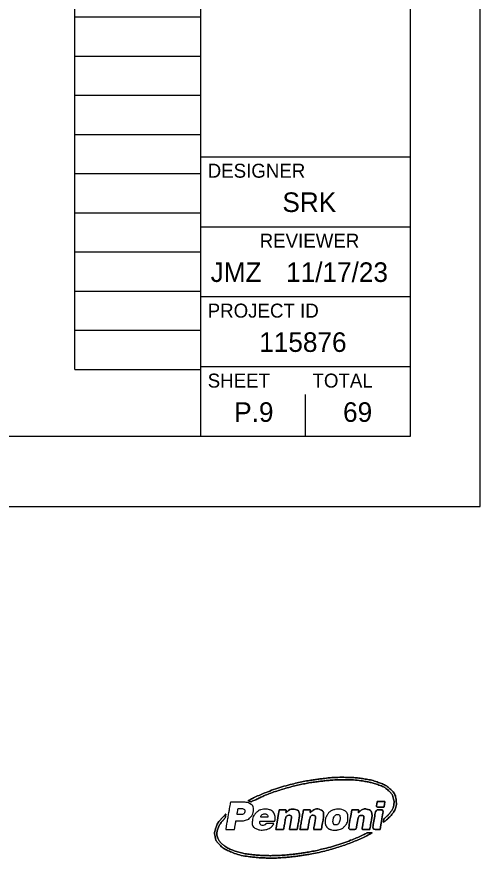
# Model space of a CAD drawing. Extents: x 0 to 63.3, y -2.5 to 22.
# Drawn here: x 30.68 to 34, y -2.51 to 3.5 of the extents above; entities that cross this region are included whole.
import ezdxf

# ---------------------------------------------------------------- set-up
doc = ezdxf.new("R2010")
doc.units = 0
for name, color, linetype in [('SH_Border', 7, 'Continuous'), ('SH_Cut_Line', 7, 'Continuous'), ('SH_Data', 7, 'Continuous')]:
    doc.layers.add(name, color=color, linetype=linetype)

msp = doc.modelspace()

# ---------------------------------------------------------------- linework, layer by layer
at = {"layer": 'SH_Border'}
for p, q in [((32, 0.5), (32, 21.5)), ((32, 2.5), (33.5, 2.5)), ((32, 2), (33.5, 2)), ((32, 1.5), (33.5, 1.5)), ((32, 1), (33.5, 1)), ((32.4801, -2.2212), (32.4295, -2.2212))]:
    msp.add_line(p, q, dxfattribs=at)
msp.add_lwpolyline([(1.5, 21.5), (33.5, 21.5), (33.5, 0.5), (1.5, 0.5)], close=True, dxfattribs=at)
for points, degree in [([(32.339, -2.1034), (32.3459, -2.1056), (32.3519, -2.1078), (32.358, -2.1095), (32.3601, -2.11), (32.3628, -2.1098), (32.3647, -2.1089), (32.3935, -2.0957), (32.4219, -2.0816), (32.4509, -2.0691), (32.4921, -2.0514), (32.5345, -2.0366), (32.5774, -2.0234), (32.6194, -2.0105), (32.6618, -1.9993), (32.7047, -1.9898), (32.7445, -1.981), (32.7845, -1.9732), (32.825, -1.968), (32.8569, -1.9639), (32.8889, -1.96), (32.921, -1.9571), (32.9462, -1.9549), (32.9715, -1.9539), (32.9968, -1.9532), (33.0519, -1.9517), (33.1068, -1.9542), (33.1614, -1.9623), (33.191, -1.9667), (33.2203, -1.9727), (33.2489, -1.9818), (33.2843, -1.9931), (33.3181, -2.0076), (33.346, -2.033), (33.3612, -2.0467), (33.3728, -2.0629), (33.3781, -2.0829), (33.3826, -2.1), (33.3843, -2.1174), (33.3813, -2.135), (33.3779, -2.1552), (33.368, -2.1723), (33.3554, -2.1881), (33.3434, -2.2033), (33.3294, -2.2165), (33.3147, -2.2291), (33.3132, -2.2304), (33.3116, -2.2321), (33.3111, -2.234), (33.3098, -2.2395), (33.3089, -2.2452), (33.3079, -2.2509), (33.3075, -2.2532), (33.3073, -2.2556), (33.3068, -2.2589), (33.3307, -2.2389), (33.3534, -2.2193), (33.372, -2.1955), (33.381, -2.184), (33.3886, -2.1716), (33.3937, -2.1578), (33.4006, -2.1393), (33.4009, -2.1203), (33.3987, -2.1009), (33.3948, -2.0665), (33.379, -2.0389), (33.3529, -2.0167), (33.329, -1.9965), (33.3014, -1.9828), (33.2722, -1.9721), (33.235, -1.9585), (33.1965, -1.9504), (33.1574, -1.9448), (33.1225, -1.9398), (33.0874, -1.9372), (33.0522, -1.9363), (32.9958, -1.9348), (32.9394, -1.9373), (32.8834, -1.9435), (32.8524, -1.947), (32.8216, -1.9515), (32.7908, -1.9561), (32.7456, -1.963), (32.7008, -1.9727), (32.6564, -1.9838), (32.5959, -1.9989), (32.5365, -2.0173), (32.4783, -2.0398), (32.4374, -2.0555), (32.3974, -2.0732), (32.3584, -2.0931), (32.3521, -2.0963), (32.346, -2.0997), (32.339, -2.1034)], 3), ([(32.339, -2.1034), (32.346, -2.0997), (32.3521, -2.0963), (32.3584, -2.0931), (32.3974, -2.0732), (32.4374, -2.0555), (32.4783, -2.0398), (32.5365, -2.0173), (32.5959, -1.9989), (32.6564, -1.9838), (32.7008, -1.9727), (32.7456, -1.963), (32.7908, -1.9561), (32.8216, -1.9515), (32.8524, -1.947), (32.8834, -1.9435), (32.9394, -1.9373), (32.9958, -1.9348), (33.0522, -1.9363), (33.0874, -1.9372), (33.1225, -1.9398), (33.1574, -1.9448), (33.1965, -1.9504), (33.235, -1.9585), (33.2722, -1.9721), (33.3014, -1.9828), (33.329, -1.9965), (33.3529, -2.0167), (33.379, -2.0389), (33.3948, -2.0665), (33.3987, -2.1009), (33.4009, -2.1203), (33.4006, -2.1393), (33.3937, -2.1578), (33.3886, -2.1716), (33.381, -2.184), (33.372, -2.1955), (33.3534, -2.2193), (33.3307, -2.2389), (33.3068, -2.2589), (33.3073, -2.2556), (33.3075, -2.2532), (33.3079, -2.2509), (33.3089, -2.2452), (33.3098, -2.2395), (33.3111, -2.234), (33.3116, -2.2321), (33.3132, -2.2304), (33.3147, -2.2291), (33.3294, -2.2165), (33.3434, -2.2033), (33.3554, -2.1881), (33.368, -2.1723), (33.3779, -2.1552), (33.3813, -2.135), (33.3843, -2.1174), (33.3826, -2.1), (33.3781, -2.0829), (33.3728, -2.0629), (33.3612, -2.0467), (33.346, -2.033), (33.3181, -2.0076), (33.2843, -1.9931), (33.2489, -1.9818), (33.2203, -1.9727), (33.191, -1.9667), (33.1614, -1.9623), (33.1068, -1.9542), (33.0519, -1.9517), (32.9968, -1.9532), (32.9715, -1.9539), (32.9462, -1.9549), (32.921, -1.9571), (32.8889, -1.96), (32.8569, -1.9639), (32.825, -1.968), (32.7845, -1.9732), (32.7445, -1.981), (32.7047, -1.9898), (32.6618, -1.9993), (32.6194, -2.0105), (32.5774, -2.0234), (32.5345, -2.0366), (32.4921, -2.0514), (32.4509, -2.0691), (32.4219, -2.0816), (32.3935, -2.0957), (32.3647, -2.1089), (32.3628, -2.1098), (32.3601, -2.11), (32.358, -2.1095), (32.3519, -2.1078), (32.3459, -2.1056), (32.339, -2.1034)], 3), ([(32.3504, -2.1223), (32.3379, -2.1163), (32.3244, -2.1142), (32.3107, -2.114), (32.2789, -2.1136), (32.2472, -2.1138), (32.2155, -2.1138), (32.2134, -2.1138), (32.2123, -2.1143), (32.212, -2.1165), (32.2083, -2.138), (32.2045, -2.1594), (32.2007, -2.1808), (32.1947, -2.2157), (32.1886, -2.2506), (32.1825, -2.2854), (32.1813, -2.2926), (32.18, -2.2998), (32.1788, -2.3071)], 3), ([(32.2521, -2.2472), (32.2596, -2.2472), (32.2665, -2.2472), (32.2735, -2.2472), (32.2865, -2.2472), (32.2994, -2.2474), (32.3122, -2.2447), (32.3288, -2.2411), (32.3438, -2.2346), (32.3556, -2.222), (32.3705, -2.2062), (32.3768, -2.1869), (32.3771, -2.1657), (32.3775, -2.1459), (32.3686, -2.1311), (32.3504, -2.1223)], 3), ([(32.2599, -2.2022), (32.2624, -2.188), (32.2648, -2.1745), (32.2673, -2.161), (32.2674, -2.1601), (32.2686, -2.1588), (32.2694, -2.1588), (32.2808, -2.1588), (32.2924, -2.1577), (32.3036, -2.1611), (32.314, -2.1642), (32.3177, -2.1706), (32.3157, -2.1812)], 3), ([(32.5317, -2.2161), (32.5277, -2.1917), (32.5147, -2.1747), (32.4908, -2.1668), (32.4777, -2.1625), (32.4642, -2.1619), (32.4507, -2.1636), (32.4286, -2.1665), (32.4095, -2.1756), (32.3941, -2.1919), (32.38, -2.2068), (32.3722, -2.2246), (32.3699, -2.2449), (32.3667, -2.2738), (32.379, -2.2978), (32.4083, -2.3074), (32.4242, -2.3126), (32.4404, -2.3128), (32.4567, -2.3104), (32.4743, -2.308), (32.4907, -2.3021), (32.5045, -2.2904), (32.5124, -2.2837), (32.5186, -2.2756), (32.523, -2.2656)], 3), ([(32.5375, -2.3087), (32.5383, -2.3089), (32.5388, -2.3091), (32.5393, -2.3091), (32.5563, -2.3091), (32.5733, -2.3091), (32.5903, -2.3092), (32.5928, -2.3092), (32.5933, -2.3078), (32.5936, -2.306), (32.595, -2.2978), (32.5963, -2.2897), (32.5978, -2.2815), (32.6009, -2.2639), (32.6038, -2.2463), (32.6075, -2.2288), (32.6095, -2.2196), (32.6141, -2.2116), (32.6242, -2.2089), (32.6372, -2.2054), (32.6506, -2.2082), (32.6485, -2.2277), (32.6469, -2.2419), (32.6441, -2.2559), (32.6417, -2.27), (32.6395, -2.2829), (32.6372, -2.2957), (32.6349, -2.3087), (32.6356, -2.3089), (32.6361, -2.3091), (32.6367, -2.3091), (32.6537, -2.3091), (32.6707, -2.3091), (32.6877, -2.3091), (32.6903, -2.3092), (32.6906, -2.3078), (32.691, -2.3057), (32.6951, -2.2817), (32.6994, -2.2578), (32.7035, -2.2339), (32.7056, -2.2218), (32.708, -2.2097), (32.7063, -2.1973), (32.7042, -2.1811), (32.6948, -2.1698), (32.679, -2.1658), (32.6573, -2.1605), (32.6376, -2.1645), (32.6205, -2.1792), (32.6167, -2.1824), (32.6132, -2.1858), (32.609, -2.1897), (32.6104, -2.1819), (32.6116, -2.1749), (32.6128, -2.1677), (32.5965, -2.1677), (32.5803, -2.1676), (32.5641, -2.1678), (32.5633, -2.1678), (32.562, -2.1692), (32.5618, -2.1701), (32.5608, -2.1744), (32.5601, -2.1788), (32.5593, -2.1831), (32.554, -2.2136), (32.5487, -2.2442), (32.5434, -2.2747), (32.5414, -2.286), (32.5395, -2.2973), (32.5375, -2.3087)], 3), ([(32.5375, -2.3087), (32.5395, -2.2973), (32.5414, -2.286), (32.5434, -2.2747), (32.5487, -2.2442), (32.554, -2.2136), (32.5593, -2.1831), (32.5601, -2.1788), (32.5608, -2.1744), (32.5618, -2.1701), (32.562, -2.1692), (32.5633, -2.1678), (32.5641, -2.1678), (32.5803, -2.1676), (32.5965, -2.1677), (32.6128, -2.1677), (32.6116, -2.1749), (32.6104, -2.1819), (32.609, -2.1897), (32.6132, -2.1858), (32.6167, -2.1824), (32.6205, -2.1792), (32.6376, -2.1645), (32.6573, -2.1605), (32.679, -2.1658), (32.6948, -2.1698), (32.7042, -2.1811), (32.7063, -2.1973), (32.708, -2.2097), (32.7056, -2.2218), (32.7035, -2.2339), (32.6994, -2.2578), (32.6951, -2.2817), (32.691, -2.3057), (32.6906, -2.3078), (32.6903, -2.3092), (32.6877, -2.3091), (32.6707, -2.3091), (32.6537, -2.3091), (32.6367, -2.3091), (32.6361, -2.3091), (32.6356, -2.3089), (32.6349, -2.3087), (32.6372, -2.2957), (32.6395, -2.2829), (32.6417, -2.27), (32.6441, -2.2559), (32.6469, -2.2419), (32.6485, -2.2277), (32.6506, -2.2082), (32.6372, -2.2054), (32.6242, -2.2089), (32.6141, -2.2116), (32.6095, -2.2196), (32.6075, -2.2288), (32.6038, -2.2463), (32.6009, -2.2639), (32.5978, -2.2815), (32.5963, -2.2897), (32.595, -2.2978), (32.5936, -2.306), (32.5933, -2.3078), (32.5928, -2.3092), (32.5903, -2.3092), (32.5733, -2.3091), (32.5563, -2.3091), (32.5393, -2.3091), (32.5388, -2.3091), (32.5383, -2.3089), (32.5375, -2.3087)], 3), ([(32.7105, -2.3086), (32.711, -2.3088), (32.7112, -2.309), (32.7114, -2.309), (32.7289, -2.309), (32.7463, -2.3091), (32.7637, -2.309), (32.7646, -2.309), (32.7662, -2.3075), (32.7664, -2.3065), (32.7695, -2.2894), (32.7723, -2.2722), (32.7755, -2.2552), (32.7773, -2.2449), (32.779, -2.2346), (32.782, -2.2247), (32.786, -2.211), (32.798, -2.2057), (32.811, -2.2084), (32.817, -2.2096), (32.8202, -2.2135), (32.8212, -2.2193), (32.8218, -2.2223), (32.822, -2.2255), (32.8215, -2.2284), (32.8199, -2.2397), (32.818, -2.2509), (32.8161, -2.2621), (32.8134, -2.2776), (32.8107, -2.2931), (32.808, -2.3085), (32.8084, -2.3087), (32.8085, -2.3089), (32.8086, -2.3089), (32.8261, -2.3089), (32.8437, -2.3091), (32.8612, -2.309), (32.8621, -2.309), (32.8636, -2.3071), (32.8638, -2.306), (32.8679, -2.2836), (32.872, -2.2613), (32.8756, -2.2389), (32.8776, -2.2269), (32.8796, -2.2148), (32.8796, -2.2027), (32.8797, -2.1872), (32.8736, -2.1738), (32.858, -2.1679), (32.8375, -2.1603), (32.8177, -2.1621), (32.7995, -2.1747), (32.7936, -2.1788), (32.7883, -2.1839), (32.7823, -2.189), (32.7835, -2.1817), (32.7846, -2.1748), (32.7858, -2.1677), (32.7694, -2.1677), (32.7535, -2.1677), (32.7376, -2.1676), (32.7347, -2.1676), (32.7349, -2.1694), (32.7345, -2.1713), (32.7304, -2.1951), (32.7262, -2.2189), (32.7221, -2.2428), (32.7182, -2.2647), (32.7144, -2.2867), (32.7105, -2.3086)], 3), ([(32.7105, -2.3086), (32.7144, -2.2867), (32.7182, -2.2647), (32.7221, -2.2428), (32.7262, -2.2189), (32.7304, -2.1951), (32.7345, -2.1713), (32.7349, -2.1694), (32.7347, -2.1676), (32.7376, -2.1676), (32.7535, -2.1677), (32.7694, -2.1677), (32.7858, -2.1677), (32.7846, -2.1748), (32.7835, -2.1817), (32.7823, -2.189), (32.7883, -2.1839), (32.7936, -2.1788), (32.7995, -2.1747), (32.8177, -2.1621), (32.8375, -2.1603), (32.858, -2.1679), (32.8736, -2.1738), (32.8797, -2.1872), (32.8796, -2.2027), (32.8796, -2.2148), (32.8776, -2.2269), (32.8756, -2.2389), (32.872, -2.2613), (32.8679, -2.2836), (32.8638, -2.306), (32.8636, -2.3071), (32.8621, -2.309), (32.8612, -2.309), (32.8437, -2.3091), (32.8261, -2.3089), (32.8086, -2.3089), (32.8085, -2.3089), (32.8084, -2.3087), (32.808, -2.3085), (32.8107, -2.2931), (32.8134, -2.2776), (32.8161, -2.2621), (32.818, -2.2509), (32.8199, -2.2397), (32.8215, -2.2284), (32.822, -2.2255), (32.8218, -2.2223), (32.8212, -2.2193), (32.8202, -2.2135), (32.817, -2.2096), (32.811, -2.2084), (32.798, -2.2057), (32.786, -2.211), (32.782, -2.2247), (32.779, -2.2346), (32.7773, -2.2449), (32.7755, -2.2552), (32.7723, -2.2722), (32.7695, -2.2894), (32.7664, -2.3065), (32.7662, -2.3075), (32.7646, -2.309), (32.7637, -2.309), (32.7463, -2.3091), (32.7289, -2.309), (32.7114, -2.309), (32.7112, -2.309), (32.711, -2.3088), (32.7105, -2.3086)], 3), ([(33.0535, -2.2166), (33.0522, -2.1945), (33.041, -2.1788), (33.0206, -2.1702), (33.0015, -2.1621), (32.9815, -2.1619), (32.9615, -2.1661), (32.9376, -2.1712), (32.9183, -2.1836), (32.9053, -2.2046), (32.904, -2.2067), (32.9028, -2.2088), (32.9016, -2.211), (32.9005, -2.2131), (32.8995, -2.2153), (32.8985, -2.2175), (32.8937, -2.2284), (32.8911, -2.2399), (32.8907, -2.252), (32.8906, -2.2544), (32.8906, -2.2568), (32.8907, -2.2592), (32.8911, -2.2671), (32.8927, -2.2743), (32.8955, -2.2805), (32.896, -2.2817), (32.8965, -2.2828), (32.8971, -2.2839), (32.8977, -2.285), (32.8983, -2.286), (32.899, -2.2871), (32.9014, -2.2907), (32.9042, -2.294), (32.9075, -2.2969), (32.9094, -2.2986), (32.9115, -2.3001), (32.9137, -2.3016), (32.9142, -2.3019), (32.9148, -2.3023), (32.9154, -2.3026), (32.9165, -2.3033), (32.9177, -2.304), (32.9189, -2.3046), (32.9208, -2.3056), (32.9227, -2.3065), (32.9247, -2.3073), (32.9358, -2.3118), (32.9474, -2.3134), (32.9593, -2.3137)], 3), ([(33.0812, -2.1678), (33.073, -2.2149), (33.0648, -2.2618), (33.0566, -2.3089), (33.0756, -2.3089), (33.0937, -2.3089), (33.1121, -2.3089), (33.1146, -2.2946), (33.117, -2.2805), (33.1195, -2.2665), (33.1219, -2.2536), (33.124, -2.2407), (33.1269, -2.2279), (33.13, -2.214), (33.1398, -2.207), (33.1532, -2.2077), (33.1618, -2.2082), (33.1669, -2.2128), (33.1677, -2.2213), (33.168, -2.2244), (33.168, -2.2275), (33.1675, -2.2306), (33.1643, -2.2495), (33.161, -2.2685), (33.1577, -2.2874), (33.1565, -2.2945), (33.1553, -2.3015), (33.1541, -2.3088), (33.1728, -2.3088), (33.1911, -2.3088), (33.2093, -2.3088), (33.2097, -2.3073), (33.2101, -2.3062), (33.2103, -2.305), (33.214, -2.2838), (33.2177, -2.2626), (33.2213, -2.2414), (33.2236, -2.2276), (33.2267, -2.2139), (33.2257, -2.1997), (33.2245, -2.1833), (33.2157, -2.1709), (33.2, -2.1664), (33.1751, -2.1593), (33.1533, -2.1654), (33.1348, -2.1834), (33.1328, -2.1853), (33.1309, -2.1872), (33.129, -2.1891), (33.1288, -2.189), (33.1285, -2.1888), (33.1283, -2.1887), (33.1295, -2.1818), (33.1306, -2.1749), (33.1318, -2.1678), (33.1147, -2.1678), (33.0982, -2.1678), (33.0812, -2.1678)], 3), ([(33.0812, -2.1678), (33.0982, -2.1678), (33.1147, -2.1678), (33.1318, -2.1678), (33.1306, -2.1749), (33.1295, -2.1818), (33.1283, -2.1887), (33.1285, -2.1888), (33.1288, -2.189), (33.129, -2.1891), (33.1309, -2.1872), (33.1328, -2.1853), (33.1348, -2.1834), (33.1533, -2.1654), (33.1751, -2.1593), (33.2, -2.1664), (33.2157, -2.1709), (33.2245, -2.1833), (33.2257, -2.1997), (33.2267, -2.2139), (33.2236, -2.2276), (33.2213, -2.2414), (33.2177, -2.2626), (33.214, -2.2838), (33.2103, -2.305), (33.2101, -2.3062), (33.2097, -2.3073), (33.2093, -2.3088), (33.1911, -2.3088), (33.1728, -2.3088), (33.1541, -2.3088), (33.1553, -2.3015), (33.1565, -2.2945), (33.1577, -2.2874), (33.161, -2.2685), (33.1643, -2.2495), (33.1675, -2.2306), (33.168, -2.2275), (33.168, -2.2244), (33.1677, -2.2213), (33.1669, -2.2128), (33.1618, -2.2082), (33.1532, -2.2077), (33.1398, -2.207), (33.13, -2.214), (33.1269, -2.2279), (33.124, -2.2407), (33.1219, -2.2536), (33.1195, -2.2665), (33.117, -2.2805), (33.1146, -2.2946), (33.1121, -2.3089), (33.0937, -2.3089), (33.0756, -2.3089), (33.0566, -2.3089), (33.0648, -2.2618), (33.073, -2.2149), (33.0812, -2.1678)], 3), ([(33.3187, -2.1089), (33.3165, -2.1214), (33.3145, -2.1336), (33.3123, -2.1458), (33.3121, -2.1468), (33.3104, -2.1481), (33.3094, -2.1481), (33.292, -2.1483), (33.2746, -2.1482), (33.2566, -2.1482), (33.2583, -2.1386), (33.2599, -2.1293), (33.2615, -2.1201), (33.2618, -2.1178), (33.2626, -2.1156), (33.2626, -2.1134), (33.2627, -2.1097), (33.2642, -2.1087), (33.2678, -2.1088), (33.2833, -2.109), (33.2989, -2.1089), (33.3144, -2.1089), (33.3157, -2.1089), (33.3171, -2.1089), (33.3187, -2.1089)], 3), ([(33.3187, -2.1089), (33.3171, -2.1089), (33.3157, -2.1089), (33.3144, -2.1089), (33.2989, -2.1089), (33.2833, -2.109), (33.2678, -2.1088), (33.2642, -2.1087), (33.2627, -2.1097), (33.2626, -2.1134), (33.2626, -2.1156), (33.2618, -2.1178), (33.2615, -2.1201), (33.2599, -2.1293), (33.2583, -2.1386), (33.2566, -2.1482), (33.2746, -2.1482), (33.292, -2.1483), (33.3094, -2.1481), (33.3104, -2.1481), (33.3121, -2.1468), (33.3123, -2.1458), (33.3145, -2.1336), (33.3165, -2.1214), (33.3187, -2.1089)], 3), ([(33.2272, -2.3324), (33.2271, -2.332), (33.2269, -2.3317), (33.2268, -2.3313), (33.2169, -2.3313), (33.207, -2.3312), (33.1971, -2.3314), (33.1946, -2.3315), (33.1918, -2.3321), (33.1895, -2.3333), (33.1523, -2.3523), (33.1142, -2.3694), (33.0753, -2.3846), (33.0173, -2.4072), (32.9581, -2.4261), (32.8978, -2.4417), (32.8548, -2.4529), (32.8115, -2.4627), (32.7676, -2.47), (32.7429, -2.4742), (32.7181, -2.4785), (32.6933, -2.4818), (32.6677, -2.4852), (32.642, -2.4878), (32.6163, -2.4901), (32.5922, -2.4922), (32.568, -2.4939), (32.5438, -2.4946), (32.5157, -2.4954), (32.4875, -2.4958), (32.4594, -2.4947), (32.4284, -2.4935), (32.3974, -2.4913), (32.3666, -2.4881), (32.3285, -2.484), (32.291, -2.4765), (32.2544, -2.465), (32.2229, -2.4551), (32.1926, -2.4424), (32.1659, -2.4224), (32.1493, -2.41), (32.1352, -2.3954), (32.1262, -2.3764), (32.1138, -2.3502), (32.1153, -2.3238), (32.1257, -2.2974), (32.1349, -2.2744), (32.1491, -2.2545), (32.1657, -2.2363), (32.1712, -2.2303), (32.1767, -2.2247), (32.1771, -2.2156), (32.1773, -2.21), (32.1788, -2.2044), (32.1799, -2.1978), (32.1785, -2.1992), (32.1778, -2.1997), (32.1771, -2.2004), (32.1676, -2.2101), (32.1577, -2.2195), (32.1487, -2.2298), (32.1292, -2.2521), (32.1134, -2.2765), (32.1052, -2.3053), (32.1004, -2.3221), (32.0991, -2.3392), (32.1023, -2.3565), (32.1071, -2.3836), (32.1213, -2.4053), (32.1412, -2.4236), (32.1638, -2.4445), (32.1905, -2.4587), (32.2189, -2.47), (32.266, -2.4888), (32.3153, -2.4991), (32.3655, -2.5049), (32.3963, -2.5084), (32.4273, -2.5106), (32.4583, -2.5119), (32.5006, -2.5137), (32.543, -2.513), (32.5852, -2.5097), (32.6195, -2.507), (32.6537, -2.5037), (32.6878, -2.4994), (32.7185, -2.4956), (32.7491, -2.4904), (32.7797, -2.4851), (32.8341, -2.4757), (32.8877, -2.4628), (32.9408, -2.4477), (32.986, -2.4349), (33.0305, -2.4201), (33.0744, -2.4032), (33.1174, -2.3866), (33.1596, -2.3681), (33.2005, -2.3468), (33.2094, -2.3421), (33.2183, -2.3372), (33.2272, -2.3324)], 3), ([(33.2272, -2.3324), (33.2183, -2.3372), (33.2094, -2.3421), (33.2005, -2.3468), (33.1596, -2.3681), (33.1174, -2.3866), (33.0744, -2.4032), (33.0305, -2.4201), (32.986, -2.4349), (32.9408, -2.4477), (32.8877, -2.4628), (32.8341, -2.4757), (32.7797, -2.4851), (32.7491, -2.4904), (32.7185, -2.4956), (32.6878, -2.4994), (32.6537, -2.5037), (32.6195, -2.507), (32.5852, -2.5097), (32.543, -2.513), (32.5006, -2.5137), (32.4583, -2.5119), (32.4273, -2.5106), (32.3963, -2.5084), (32.3655, -2.5049), (32.3153, -2.4991), (32.266, -2.4888), (32.2189, -2.47), (32.1905, -2.4587), (32.1638, -2.4445), (32.1412, -2.4236), (32.1213, -2.4053), (32.1071, -2.3836), (32.1023, -2.3565), (32.0991, -2.3392), (32.1004, -2.3221), (32.1052, -2.3053), (32.1134, -2.2765), (32.1292, -2.2521), (32.1487, -2.2298), (32.1577, -2.2195), (32.1676, -2.2101), (32.1771, -2.2004), (32.1778, -2.1997), (32.1785, -2.1992), (32.1799, -2.1978), (32.1788, -2.2044), (32.1773, -2.21), (32.1771, -2.2156), (32.1767, -2.2247), (32.1712, -2.2303), (32.1657, -2.2363), (32.1491, -2.2545), (32.1349, -2.2744), (32.1257, -2.2974), (32.1153, -2.3238), (32.1138, -2.3502), (32.1262, -2.3764), (32.1352, -2.3954), (32.1493, -2.41), (32.1659, -2.4224), (32.1926, -2.4424), (32.2229, -2.4551), (32.2544, -2.465), (32.291, -2.4765), (32.3285, -2.484), (32.3666, -2.4881), (32.3974, -2.4913), (32.4284, -2.4935), (32.4594, -2.4947), (32.4875, -2.4958), (32.5157, -2.4954), (32.5438, -2.4946), (32.568, -2.4939), (32.5922, -2.4922), (32.6163, -2.4901), (32.642, -2.4878), (32.6677, -2.4852), (32.6933, -2.4818), (32.7181, -2.4785), (32.7429, -2.4742), (32.7676, -2.47), (32.8115, -2.4627), (32.8548, -2.4529), (32.8978, -2.4417), (32.9581, -2.4261), (33.0173, -2.4072), (33.0753, -2.3846), (33.1142, -2.3694), (33.1523, -2.3523), (33.1895, -2.3333), (33.1918, -2.3321), (33.1946, -2.3315), (33.1971, -2.3314), (33.207, -2.3312), (33.2169, -2.3313), (33.2268, -2.3313), (33.2269, -2.3317), (33.2271, -2.332), (33.2272, -2.3324)], 3), ([(32.3157, -2.1812), (32.3133, -2.1931), (32.3045, -2.2013), (32.292, -2.202), (32.2815, -2.2026), (32.271, -2.2022), (32.2599, -2.2022)], 3), ([(32.4295, -2.2212), (32.4308, -2.2089), (32.4404, -2.1992), (32.4527, -2.1972), (32.4588, -2.1962), (32.4646, -2.1962), (32.4701, -2.1994), (32.4776, -2.2037), (32.4814, -2.2117), (32.4801, -2.2212)], 3), ([(32.5305, -2.2496), (32.5327, -2.2382), (32.5335, -2.2271), (32.5317, -2.2161)], 2), ([(32.9465, -2.253), (32.9474, -2.2368), (32.9498, -2.223), (32.9589, -2.2114), (32.9639, -2.205), (32.9706, -2.2014), (32.9789, -2.2012), (32.9876, -2.2011), (32.9936, -2.2046), (32.9957, -2.2131), (32.9973, -2.2194), (32.9977, -2.2263), (32.9973, -2.2328)], 3), ([(32.9593, -2.3137), (32.9665, -2.3129), (32.9737, -2.3125), (32.9808, -2.3112), (33, -2.3078), (33.0169, -2.2996), (33.0301, -2.2849), (33.0474, -2.2655), (33.0549, -2.2423), (33.0535, -2.2166)], 3), ([(33.284, -2.3074), (33.2656, -2.3074), (33.2475, -2.3074), (33.2287, -2.3074), (33.2369, -2.2604), (33.2451, -2.2138), (33.2533, -2.167), (33.2716, -2.167), (33.2898, -2.167), (33.3086, -2.167), (33.3004, -2.2138), (33.2923, -2.2604), (33.284, -2.3074)], 3), ([(33.284, -2.3074), (33.2923, -2.2604), (33.3004, -2.2138), (33.3086, -2.167), (33.2898, -2.167), (33.2716, -2.167), (33.2533, -2.167), (33.2451, -2.2138), (33.2369, -2.2604), (33.2287, -2.3074), (33.2475, -2.3074), (33.2656, -2.3074), (33.284, -2.3074)], 3), ([(32.1788, -2.3071), (32.1797, -2.3073), (32.1802, -2.3076), (32.1807, -2.3076), (32.2002, -2.3076), (32.2196, -2.3076), (32.239, -2.3077), (32.2415, -2.3077), (32.2418, -2.3061), (32.2421, -2.3044), (32.2441, -2.2931), (32.246, -2.2818), (32.248, -2.2705), (32.2493, -2.2628), (32.2507, -2.2551), (32.2521, -2.2472)], 3), ([(32.523, -2.2656), (32.5057, -2.2656), (32.4889, -2.2656), (32.4722, -2.2657), (32.4711, -2.2657), (32.47, -2.2667), (32.4689, -2.2675), (32.4647, -2.2704), (32.461, -2.2745), (32.4563, -2.2762), (32.4403, -2.2821), (32.4231, -2.2728), (32.4237, -2.2544), (32.4239, -2.2506), (32.425, -2.2495), (32.4289, -2.2495), (32.461, -2.2497), (32.4932, -2.2496), (32.5253, -2.2496), (32.5271, -2.2496), (32.5288, -2.2496), (32.5305, -2.2496)], 3), ([(32.9973, -2.2328), (32.9968, -2.2432), (32.9937, -2.2531), (32.9885, -2.2621), (32.9828, -2.2721), (32.9729, -2.277), (32.9623, -2.2755), (32.9557, -2.2746), (32.9512, -2.2709), (32.9491, -2.2647), (32.9476, -2.2604), (32.9471, -2.2557), (32.9465, -2.253)], 3)]:
    msp.add_open_spline(points, degree=degree, dxfattribs=at)
at = {"layer": 'SH_Cut_Line'}
msp.add_lwpolyline([(0, 0), (34, 0), (34, 22), (0, 22)], close=True, dxfattribs=at)
at = {"layer": 'SH_Data'}
for p, q in [((31.1, 0.98), (31.1, 21.14)), ((32, 0.98), (32, 21.14)), ((31.1, 3.5), (32, 3.5)), ((31.1, 3.22), (32, 3.22)), ((31.1, 2.94), (32, 2.94)), ((31.1, 2.66), (32, 2.66)), ((31.1, 2.38), (32, 2.38)), ((31.1, 2.1), (32, 2.1)), ((31.1, 1.82), (32, 1.82)), ((31.1, 1.54), (32, 1.54)), ((31.1, 1.26), (32, 1.26)), ((31.1, 0.98), (32, 0.98)), ((32.75, 0.5), (32.75, 0.8)), ((32.375, 0.675), (32.375, 0.675))]:
    msp.add_line(p, q, dxfattribs=at)

# ---------------------------------------------------------------- texts
for s, height, p in [('DESIGNER', 0.1, (32.05, 2.35)), ('SRK', 0.14, (32.5847, 2.105)), ('REVIEWER', 0.1, (32.4218, 1.85)), ('JMZ', 0.14, (32.0712, 1.605)), ('11/17/23', 0.14, (32.6113, 1.605)), ('PROJECT ID', 0.1, (32.05, 1.35)), ('115876', 0.14, (32.4191, 1.105)), ('SHEET', 0.1, (32.05, 0.85)), ('TOTAL', 0.1, (32.8, 0.85)), ('P.9', 0.14, (32.2399, 0.605)), ('69', 0.14, (33.0188, 0.605))]:
    msp.add_text(s, height=height, dxfattribs=at).set_placement(p)

doc.saveas('drawing.dxf')
